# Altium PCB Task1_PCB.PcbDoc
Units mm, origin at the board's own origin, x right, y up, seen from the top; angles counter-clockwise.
Board outline 49.02 x 33.27 mm, 2 copper layers (Top Layer, Bottom Layer); 16 components, 13 nets, 96 pads, 5 vias.
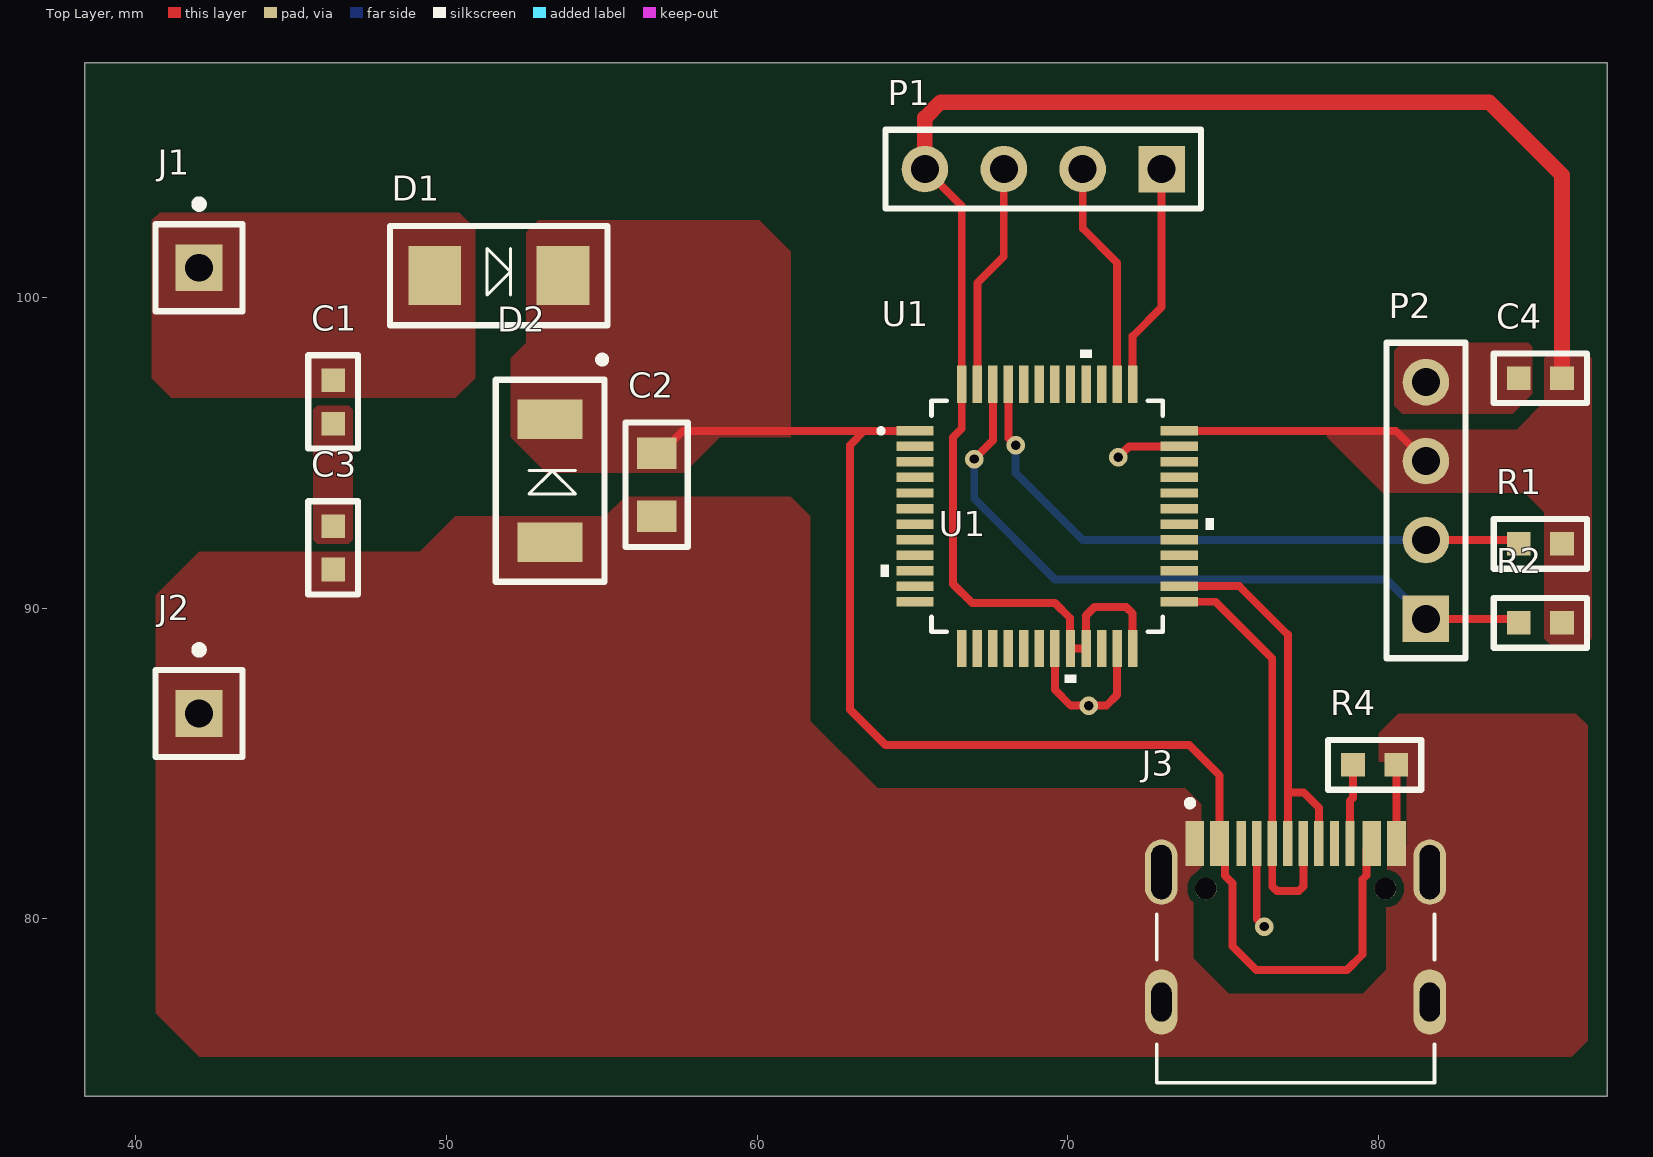
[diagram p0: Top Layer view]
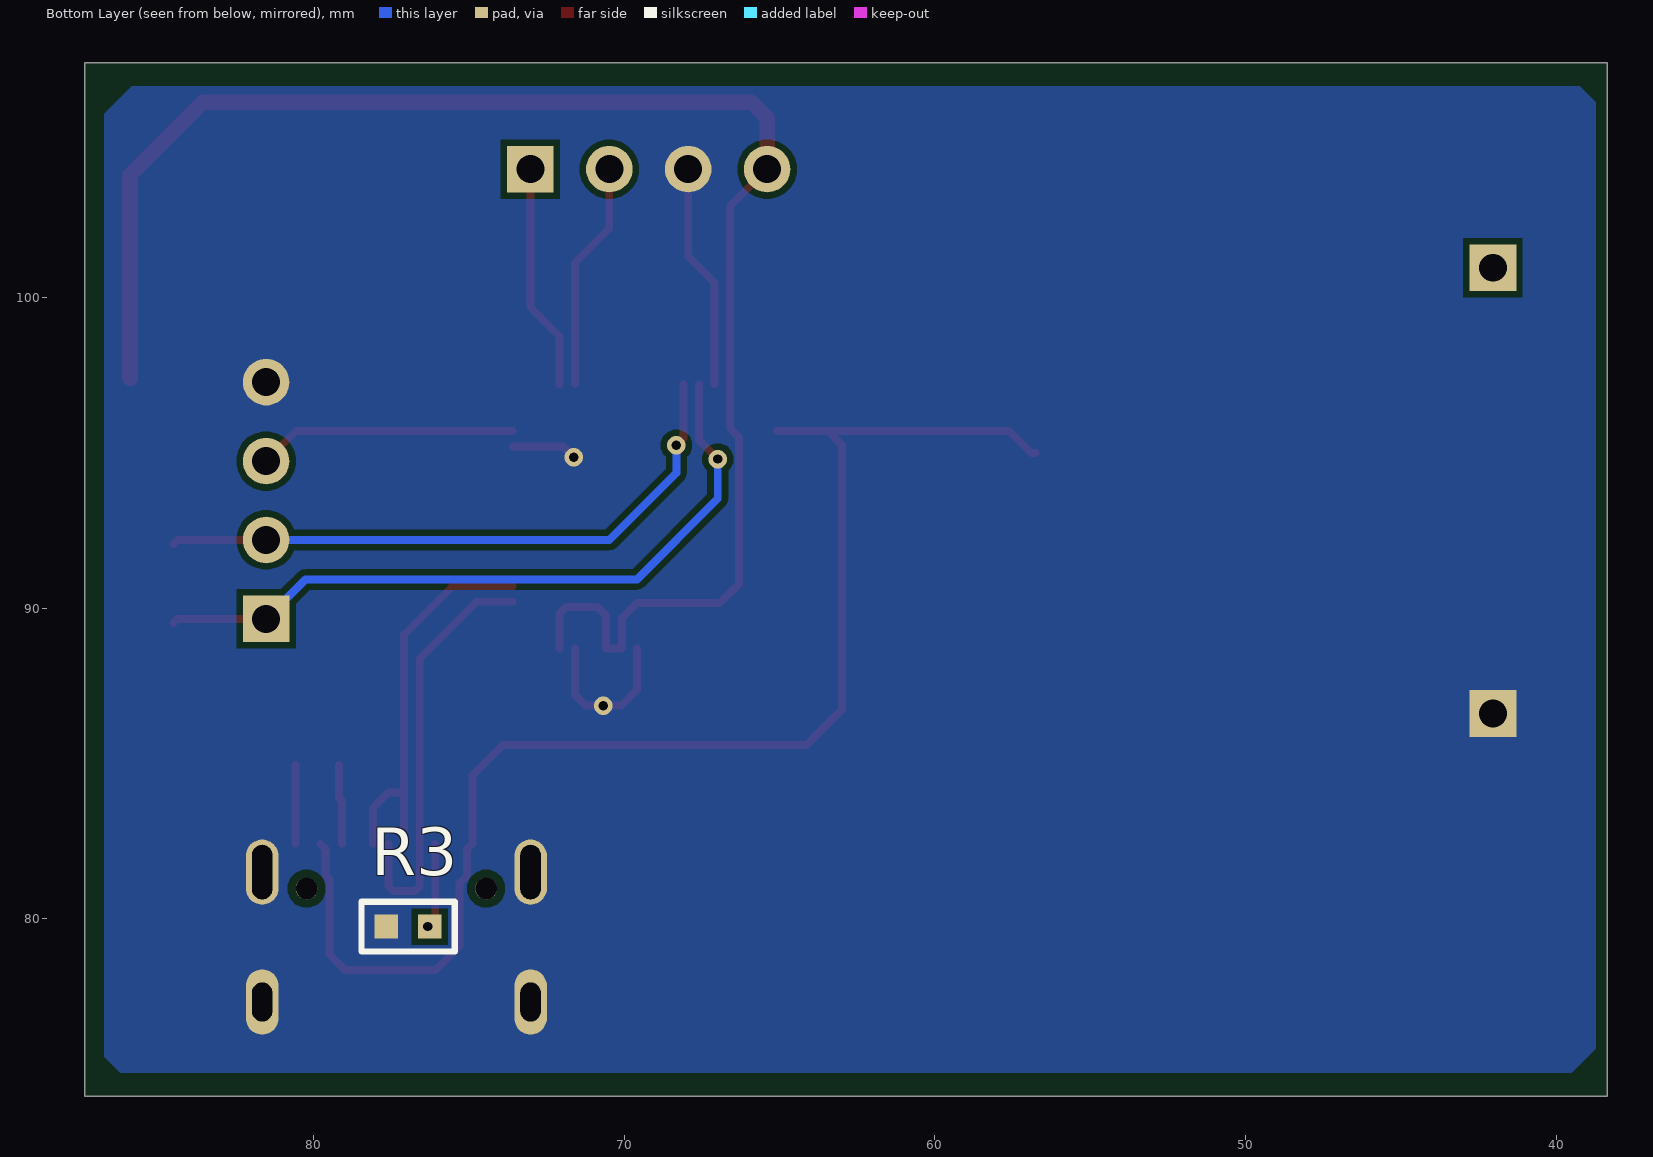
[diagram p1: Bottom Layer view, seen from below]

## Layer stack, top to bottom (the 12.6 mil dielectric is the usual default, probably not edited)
Top Solder: solder mask 0.0102, Solder Resist, Dk 3.5
Top Layer: signal copper 0.0356
Dielectric 1: dielectric 0.32, FR-4, Dk 4.8
Bottom Layer: signal copper 0.0356
Bottom Solder: solder mask 0.0102, Solder Resist, Dk 3.5

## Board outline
38.354,74.295 38.354,107.569 87.376,107.569 87.376,74.295

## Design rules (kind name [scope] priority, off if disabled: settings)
Clearance [All] p1: gap=0.2 ignorepadtopadclearanceinfootprint=TRUE except(0.254: Arc-Via Arc-Text Arc-Hole Track-Via Track-Text Track-Hole SMDPad-Via SMDPad-Text SMDPad-Hole THPad-Via THPad-Text THPad-Hole Via-Via Via-Text Via-Hole Fill-Text Fill-Hole Poly-Text Poly-Hole Region-Text Region-Hole Text-Text Text-Hole)
PolygonConnect [All] p1: connectstyle=Direct reliefconductorwidth=0.254 reliefentries=4 polygonreliefangle="90 Angle" airgapwidth=0.254
RoutingVias [All] p1: holewidth=0.711 width=1.27 viastyle="Through Hole" minholewidth=0.711 minwidth=1.27 maxholewidth=0.711 maxwidth=1.27
SolderMaskExpansion [All] p1: expansion=0.102 istentingtop=FALSE
SupplyNets "Schematic Supply Nets" [InNet('GND')] p1: voltage=0.000
Width [All] p1: maxlimit=1 minlimit=0.254 preferedwidth=0.254
30 further rules are at their usual default settings.

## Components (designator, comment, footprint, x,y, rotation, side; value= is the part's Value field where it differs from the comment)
C1 "100nF/50V/0603" C0603 46.355,96.647 r90 top
C2 "0805" C0805 56.769,93.98 r90 top
C3 "100nF/50V/0603" C0603 46.355,91.948 r90 top
C4 "0603" C0603 85.217,97.409 r0 top
D1 "S1M" S1M 51.689,100.711 r0 top
D2 "SMBJ18CA-Q" SMBJ18CA-Q 53.34,94.107 r90 top
J1 "Socket" PIN1 42.037,100.965 r0 top
J2 "Socket" PIN1 42.037,86.614 r0 top
J3 "USB-C" HRO_TYPE-C-31-M-12 77.339,77.328 r0 top
P1 "Header 4" HDR1X4 73.025,104.14 r180 top
P2 "Header 4" HDR1X4 81.534,89.662 r90 top
R1 "0603" R0603 85.217,92.075 r0 top
R2 "0603" R0603 85.217,89.535 r0 top
R3 "0603" R0603 76.962,79.756 r180 bottom
R4 "0603" R0603 79.883,84.963 r180 top
U1 "STM32G431CBT6" LQFP48-7x7mm 69.342,92.964 r0 top

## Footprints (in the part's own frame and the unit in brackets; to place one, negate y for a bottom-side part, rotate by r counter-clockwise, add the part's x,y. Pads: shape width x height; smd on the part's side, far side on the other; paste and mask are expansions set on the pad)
C0603 [mil]
  rect 30x30 smd: 1(-27.5,0) 2(27.5,0)
  silkscreen extent -59,-31 59,31, body extent -32,-15 32,15, height 19
C0805 [mil]
  rect 40x50 smd: 1(-40,0) 2(40,0)
  silkscreen extent -79,-39 79,39, body extent -41,-25 40,25, height 26
HDR1X4 [mm] "Connector; Header; 4 Position"
  rect 1.5x1.5 hole 0.9: 1(0,0)
  round 1.5 hole 0.9: 2(2.54,0) 3(5.08,0) 4(7.62,0)
  silkscreen extent -1.27,-1.27 8.89,1.27
HRO_TYPE-C-31-M-12 [mm]
  rect 0.6x1.45 smd paste+0 mask+0.102: A1B12(-3.25,5.095) A4B9(-2.45,5.095) B1A12(3.25,5.095) B4A9(2.45,5.095)
  rect 0.3x1.45 smd paste+0 mask+0.102: A5(-1.25,5.095) A6(-0.25,5.095) A7(0.25,5.095) A8(1.25,5.095) B5(1.75,5.095) B6(0.75,5.095) B7(-0.75,5.095) B8(-1.75,5.095)
  oval 1.05x2.1 hole 0.65 slot 1.75 at 90 deg mask+0.102: S1(-4.32,4.18) S2(4.32,4.18)
  oval 1.05x2.1 hole 0.65 slot 1.25 at 90 deg mask+0.102: S3(-4.32,0) S4(4.32,0)
  round 0.7 hole 0.7 unplated mask+0: ""(-2.89,3.65) ""(2.89,3.65)
  silkscreen extent -4.47,-2.6 4.47,6.5
LQFP48-7x7mm [mm]
  rect 1.194x0.305 smd paste+0 mask+0: 1(-4.25,2.75) 2(-4.25,2.25) 3(-4.25,1.75) 4(-4.25,1.25) 5(-4.25,0.75) 6(-4.25,0.25) 7(-4.25,-0.25) 8(-4.25,-0.75) 9(-4.25,-1.25) 10(-4.25,-1.75) 11(-4.25,-2.25) 12(-4.25,-2.75) 25(4.25,-2.75) 26(4.25,-2.25) 27(4.25,-1.75) 28(4.25,-1.25) 29(4.25,-0.75) 30(4.25,-0.25) 31(4.25,0.25) 32(4.25,0.75) 33(4.25,1.25) 34(4.25,1.75) 35(4.25,2.25) 36(4.25,2.75)
  rect 0.305x1.194 smd paste+0 mask+0: 13(-2.75,-4.25) 14(-2.25,-4.25) 15(-1.75,-4.25) 16(-1.25,-4.25) 17(-0.75,-4.25) 18(-0.25,-4.25) 19(0.25,-4.25) 20(0.75,-4.25) 21(1.25,-4.25) 22(1.75,-4.25) 23(2.25,-4.25) 24(2.75,-4.25) 37(2.75,4.25) 38(2.25,4.25) 39(1.75,4.25) 40(1.25,4.25) 41(0.75,4.25) 42(0.25,4.25) 43(-0.25,4.25) 44(-0.75,4.25) 45(-1.25,4.25) 46(-1.75,4.25) 47(-2.25,4.25) 48(-2.75,4.25)
  silkscreen extent -5.43,-5.35 5.35,5.35, body extent -4.5,-4.5 4.5,4.5, height 1.6
PIN1 [mm] "Connector; Plug"
  rect 1.5x1.5 hole 0.9: 1(0,0)
  silkscreen extent -1.4,-1.4 1.4,2.17
R0603 [mil]
  rect 30x30 smd: 1(-27.5,0) 2(27.5,0)
  silkscreen extent -59,-31 59,31, body extent -32,-15 32,15, height 19
S1M [mm]
  rect 1.7x1.9 smd: A(-2.065,0) K(2.065,0)
  silkscreen extent -3.5,-1.6 3.5,1.6, body extent -2.57,-1.28 2.57,1.28, height 2.5
SMBJ18CA-Q [mm]
  rect 1.27x2.1 smd: A(-1.98,0) K(1.98,0)
  silkscreen extent -3.25,-1.75 3.97,1.75, body extent -2.68,-1.81 2.68,1.81, height 2.65

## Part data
C1 C3 C4: library part C0603
C2: library part C0805
D1: "VR=1000V IF=1A 6.6pF Trr=1.8us P=1.4W", Average Rectified Current=1A, Capacitance=12pF, Case/Package=DO-214AC, Forward Voltage=1V, Manufacturer="ON Semiconductor / Fairchild", Max Forward Surge Current (Ifsm)=30A, Max Operating Temperature=150°C, Max Repetitive Reverse Voltage (Vrrm)=1kV, Max Reverse Current=1uA, Max Surge Current=40A, Min Operating Temperature=-55°C, Package Quantity=1, Power Dissipation=1.4W, Supplier Part Number 1=S1MFSTR-ND
J3: "USB-C (USB TYPE-C) USB 3.2 Gen 2 (USB 3.1 Gen 2, Superspeed + (USB 3.1)) Receptacle Connector 24 Position Surface Mount, Through Hole", Package=None
P1 P2: "Header, 4-Pin"
R1 R2 R3 R4: library part R0603
U1: "Mainstream Arm Cortex-M4 MCU 170 MHz with 128 Kbytes of Flash memory, Math Accelerator, Medium Analog level integration", Manufacturer_Name=STMicroelectronics

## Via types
v1: diameter 0.6, hole 0.3, Top Layer to Bottom Layer, 5 vias

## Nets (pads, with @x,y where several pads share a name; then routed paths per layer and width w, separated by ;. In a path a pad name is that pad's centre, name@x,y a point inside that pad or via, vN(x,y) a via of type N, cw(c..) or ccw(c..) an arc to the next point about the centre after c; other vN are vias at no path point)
3.3V: C4.2 P1.4 P2.3 R1.2 R2.2 U1.20 U1.21 U1.24 U1.36 U1.48 | length 61.8
  Top Layer w0.254: P1.4 66.592,102.953 U1.48 66.592,95.787 66.312,95.506 66.312,90.787 66.929,90.17 69.596,90.17 70.071,89.695 70.071,88.735 U1.20 U1.21 70.592,89.769 70.866,90.043 71.882,90.043 72.092,89.833 U1.24 ; U1.36 80.562,95.714 P2.3
  Top Layer w0.5: P1.4 65.405,105.791 65.913,106.299 83.566,106.299 85.915,103.95 C4.2
DN: J3.A7 J3.B7 U1.25 | length 13.6
  Top Layer w0.254: U1.25 74.759,90.214 76.589,88.384 J3.B7 76.589,81.048 76.738,80.899 77.44,80.899 77.589,81.048 J3.A7
DP: J3.A6 J3.B6 U1.26 | length 13.2
  Top Layer w0.254: U1.26 75.529,90.714 77.089,89.154 77.089,84.074 ; J3.A6 77.089,84.074 ; J3.B6 78.089,83.582 77.597,84.074 77.089,84.074
GND: C2.1 C3.1 C4.1 D2.A J2.1 J3.A1B12 J3.B1A12 J3.S1 J3.S2 J3.S3 J3.S4 P1.3 P2.4 R3.1 R4.1 U1.19 U1.23 U1.35 U1.47 | length 17.1
  Top Layer w0.254: U1.47@67.1,97.214 67.1,100.48 67.945,101.325 P1.3 ; U1.19 69.592,87.38 70.104,86.868 71.247,86.868 71.592,87.213 U1.23 ; v1(71.628,94.869) 71.973,95.214 U1.35 ; R4.1 80.589,84.955 J3.B1A12
  other v1: 70.675,86.868
NetC1_1: C1.1 C3.2
NetC1_2: C1.2 D1.A J1.1
NetJ3_A5: J3.A5 R3.2 | length 2.8
  Top Layer w0.254: J3.A5 76.089,79.994 v1(76.327,79.756)
NetJ3_B5: J3.B5 R4.2 | length 2.6
  Top Layer w0.254: J3.B5 79.089,83.806 79.184,83.901 R4.2
SCL: P2.2 R1.1 U1.45 | length 20.1
  Top Layer w0.254: U1.45 68.092,95.484 v1(68.326,95.25) ; P2.2 84.391,92.202 R1.1
  Bottom Layer w0.254: v1(68.326,95.25) 68.326,94.361 70.485,92.202 P2.2
SDA: P2.1 R2.1 U1.46 | length 23.1
  Top Layer w0.254: v1(66.992,94.805) 67.592,95.405 U1.46 ; P2.1 84.391,89.662 R2.1
  Bottom Layer w0.254: v1(66.992,94.805) 66.992,93.535 69.596,90.932 80.264,90.932 P2.1
SWCLK: P1.2 U1.38 | length 7.4
  Top Layer w0.254: P1.2 70.485,102.235 71.592,101.128 U1.38
SWDIO: P1.1 U1.37 | length 7.3
  Top Layer w0.254: U1.37 72.092,98.762 73.025,99.695 P1.1
Vin: C2.2 D1.K D2.K J3.A4B9 J3.B4A9 U1.1 | length 44.6
  Top Layer w0.254: C2.2 56.896,94.996 57.614,95.714 63.456,95.714 ; U1.1 63.456,95.714 ; J3.B4A9 79.616,82.25 79.616,81.399 79.498,81.281 79.498,78.863 78.994,78.359 76.073,78.359 75.311,79.121 75.311,81.15 75.062,81.399 75.062,82.25 J3.A4B9 74.889,84.623 73.914,85.598 64.135,85.598 62.992,86.741 62.992,95.25 63.456,95.714
pads on no net: J3. J3.A8 J3.B8 U1.2 U1.3 U1.4 U1.5 U1.6 U1.7 U1.8 U1.9 U1.10 U1.11 U1.12 U1.13 U1.14 U1.15 U1.16 U1.17 U1.18 U1.22 U1.27 U1.28 U1.29 U1.30 U1.31 U1.32 U1.33 U1.34 U1.39 U1.40 U1.41 U1.42 U1.43 U1.44

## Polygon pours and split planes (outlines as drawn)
GND on Top Layer "NONET_L-01_P-001" (solid, pour order 5): 80.518,98.298 80.518,96.52 80.772,96.266 84.328,96.266 84.963,96.901 84.963,98.425 84.836,98.552 80.772,98.552
3.3V on Top Layer "NONET_L-01_P-001" (solid, pour order 4): 84.455,95.758 85.344,96.647 85.344,98.044 85.471,98.171 86.741,98.171 86.868,98.044 86.868,89.027 86.614,88.773 85.598,88.773 85.344,89.027 85.344,93.091 84.709,93.726 80.137,93.726 78.105,95.758 77.724,95.758
GND on Top Layer "NONET_L-01_P-001" (solid, pour order 3): 40.64,90.424 42.037,91.821 49.149,91.821 50.292,92.964 55.118,92.964 55.753,93.599 61.087,93.599 61.722,92.964 61.722,86.36 63.881,84.201 73.787,84.201 74.295,83.693 74.295,81.661 74.041,81.407 74.041,78.74 75.184,77.597 79.502,77.597 80.264,78.359 80.264,84.328 80.01,84.582 80.01,85.979 80.645,86.614 86.36,86.614 86.741,86.233 86.741,76.073 86.233,75.565 42.037,75.565 40.64,76.962
Vin on Top Layer "NONET_L-01_P-001" (solid, pour order 2): 52.578,102.108 52.578,98.552 52.07,98.044 52.07,95.504 53.213,94.361 57.658,94.361 58.801,95.504 61.087,95.504 61.087,101.473 60.071,102.489 52.959,102.489
NetC1_1 on Top Layer "NONET_L-01_P-001" (solid, pour order 1): 45.72,96.393 45.72,92.202 45.847,92.075 46.863,92.075 46.99,92.202 46.99,96.393 46.863,96.52 45.847,96.52
NetC1_2 on Top Layer "NONET_L-01_P-001" (solid, pour order 0): 40.513,102.489 40.513,97.409 41.148,96.774 50.292,96.774 50.927,97.409 50.927,102.235 50.419,102.743 40.767,102.743
GND on Bottom Layer "NONET_L-01_P-001" (solid, pour order 6): 38.735,75.819 39.497,75.057 86.233,75.057 86.741,75.565 86.741,105.918 85.852,106.807 39.243,106.807 38.735,106.299

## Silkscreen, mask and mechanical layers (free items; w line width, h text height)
Board OutLine:
  the board outline again, w0.254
